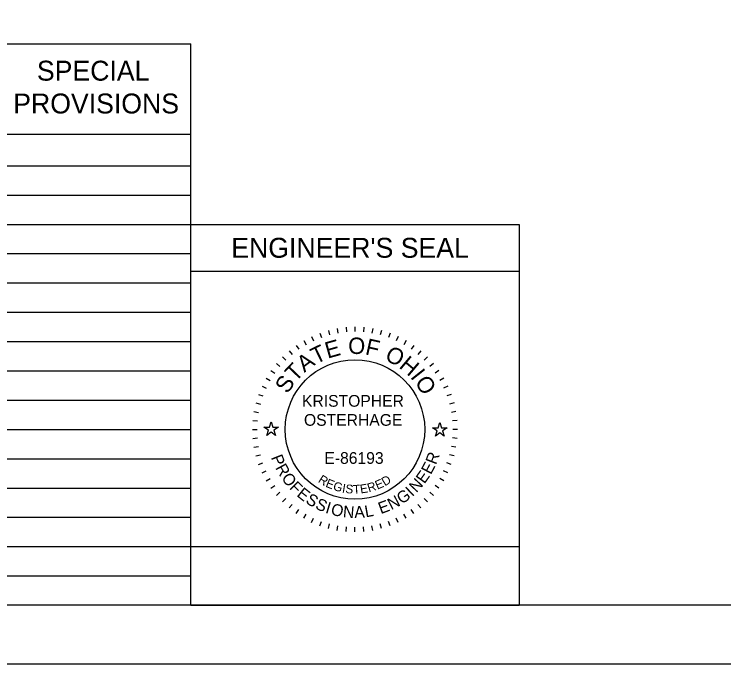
# Model space of a CAD drawing. Extents: x 0 to 64.8, y -5 to 22.
# Drawn here: x 22.09 to 28.15, y 0 to 5.54 of the extents above; entities that cross this region are included whole.
import ezdxf

# ---------------------------------------------------------------- set-up
doc = ezdxf.new("R2010")
doc.units = 0
for name, color, linetype in [('SH_Border', 7, 'Continuous'), ('SH_Cut_Line', 7, 'Continuous'), ('SH_Data', 7, 'Continuous'), ('SH_Text', 7, 'Continuous')]:
    doc.layers.add(name, color=color, linetype=linetype)

msp = doc.modelspace()

# ---------------------------------------------------------------- linework, layer by layer
at = {"layer": 'SH_Border'}
msp.add_lwpolyline([(1.5, 21.5), (33.5, 21.5), (33.5, 0.5), (1.5, 0.5)], close=True, dxfattribs=at)
at = {"layer": 'SH_Cut_Line'}
msp.add_lwpolyline([(0, 0), (34, 0), (34, 22), (0, 22)], close=True, dxfattribs=at)
at = {"layer": 'SH_Data'}
for p, q in [((10.15, 5.2917), (23.6, 5.2917)), ((23.6, 0.5), (23.6, 5.2917)), ((10.15, 4.5209), (23.6, 4.5209)), ((10.15, 4.25), (23.6, 4.25)), ((10.15, 4), (23.6, 4)), ((10.15, 3.75), (23.6, 3.75)), ((23.6, 0.5), (23.6, 3.75)), ((23.6, 3.75), (26.4, 3.75)), ((26.4, 3.75), (26.4, 0.5)), ((10.15, 3.5), (23.6, 3.5)), ((23.6, 3.35), (26.4, 3.35)), ((10.15, 3.25), (23.6, 3.25)), ((10.15, 3), (23.6, 3)), ((24.8481, 2.8617), (24.855, 2.8223)), ((24.9237, 2.8717), (24.9272, 2.8318)), ((25, 2.875), (25, 2.835)), ((25.0763, 2.8717), (25.0728, 2.8318)), ((25.1519, 2.8617), (25.145, 2.8223)), ((24.6302, 2.793), (24.6471, 2.7568)), ((24.7007, 2.8222), (24.7144, 2.7846)), ((24.7735, 2.8452), (24.7839, 2.8065)), ((25.2265, 2.8452), (25.2161, 2.8065)), ((25.2993, 2.8222), (25.2856, 2.7846)), ((25.3698, 2.793), (25.3529, 2.7568)), ((10.15, 2.75), (23.6, 2.75)), ((24.5625, 2.7578), (24.5825, 2.7231)), ((25.4375, 2.7578), (25.4175, 2.7231)), ((24.4376, 2.6703), (24.4633, 2.6396)), ((24.4981, 2.7168), (24.5211, 2.684)), ((25.5019, 2.7168), (25.4789, 2.684)), ((25.5624, 2.6703), (25.5367, 2.6396)), ((24.3813, 2.6187), (24.4096, 2.5904)), ((25.6187, 2.6187), (25.5904, 2.5904)), ((24.3297, 2.5624), (24.3604, 2.5367)), ((25.6703, 2.5624), (25.6396, 2.5367)), ((10.15, 2.5), (23.6, 2.5)), ((24.2832, 2.5019), (24.316, 2.4789)), ((25.7168, 2.5019), (25.684, 2.4789)), ((24.2422, 2.4375), (24.2769, 2.4175)), ((25.7578, 2.4375), (25.7231, 2.4175)), ((24.207, 2.3698), (24.2432, 2.3529)), ((25.793, 2.3698), (25.7568, 2.3529)), ((10.15, 2.25), (23.6, 2.25)), ((24.1778, 2.2993), (24.2154, 2.2856)), ((25.8222, 2.2993), (25.7846, 2.2856)), ((24.1548, 2.2265), (24.1935, 2.2161)), ((25.8452, 2.2265), (25.8065, 2.2161)), ((24.1383, 2.1519), (24.1777, 2.145)), ((25.8617, 2.1519), (25.8223, 2.145)), ((24.1283, 2.0763), (24.1682, 2.0728)), ((25.8717, 2.0763), (25.8318, 2.0728)), ((10.15, 2), (23.6, 2)), ((24.125, 2), (24.165, 2)), ((25.875, 2), (25.835, 2)), ((24.1283, 1.9237), (24.1682, 1.9272)), ((25.8717, 1.9237), (25.8318, 1.9272)), ((24.1383, 1.8481), (24.1777, 1.855)), ((25.8617, 1.8481), (25.8223, 1.855)), ((24.1548, 1.7735), (24.1935, 1.7839)), ((25.8452, 1.7735), (25.8065, 1.7839)), ((10.15, 1.75), (23.6, 1.75)), ((24.1778, 1.7007), (24.2154, 1.7144)), ((25.8222, 1.7007), (25.7846, 1.7144)), ((24.207, 1.6302), (24.2432, 1.6471)), ((25.793, 1.6302), (25.7568, 1.6471)), ((24.2422, 1.5625), (24.2769, 1.5825)), ((25.7578, 1.5625), (25.7231, 1.5825)), ((24.2832, 1.4981), (24.316, 1.5211)), ((25.7168, 1.4981), (25.684, 1.5211)), ((10.15, 1.5), (23.6, 1.5)), ((24.3297, 1.4376), (24.3604, 1.4633)), ((25.6703, 1.4376), (25.6396, 1.4633)), ((24.3813, 1.3813), (24.4096, 1.4096)), ((25.6187, 1.3813), (25.5904, 1.4096)), ((24.4376, 1.3297), (24.4633, 1.3604)), ((25.5624, 1.3297), (25.5367, 1.3604)), ((24.4981, 1.2832), (24.5211, 1.316)), ((24.5625, 1.2422), (24.5825, 1.2769)), ((25.4375, 1.2422), (25.4175, 1.2769)), ((25.5019, 1.2832), (25.4789, 1.316)), ((10.15, 1.25), (23.6, 1.25)), ((24.6302, 1.207), (24.6471, 1.2432)), ((24.7007, 1.1778), (24.7144, 1.2154)), ((25.2993, 1.1778), (25.2856, 1.2154)), ((25.3698, 1.207), (25.3529, 1.2432)), ((24.7735, 1.1548), (24.7839, 1.1935)), ((24.8481, 1.1383), (24.855, 1.1777)), ((24.9237, 1.1283), (24.9272, 1.1682)), ((25, 1.125), (25, 1.165)), ((25.0763, 1.1283), (25.0728, 1.1682)), ((25.1519, 1.1383), (25.145, 1.1777)), ((25.2265, 1.1548), (25.2161, 1.1935)), ((10.15, 1), (23.6, 1)), ((10.15, 0.75), (23.6, 0.75)), ((23.6, 0.5), (26.4, 0.5))]:
    msp.add_line(p, q, dxfattribs=at)
for points in [[(24.2236, 2.02), (24.2705, 2.02), (24.285, 2.0645), (24.2995, 2.02), (24.3464, 2.02), (24.3085, 1.9924), (24.323, 1.9478), (24.285, 1.9754), (24.247, 1.9478), (24.2615, 1.9924)], [(25.6627, 2.0146), (25.7096, 2.0146), (25.7241, 2.0591), (25.7386, 2.0146), (25.7855, 2.0146), (25.7476, 1.987), (25.7621, 1.9424), (25.7241, 1.97), (25.6861, 1.9424), (25.7006, 1.987)], [(23.6, 0.5), (23.6, 1), (26.4, 1), (26.4, 0.5)]]:
    msp.add_lwpolyline(points, close=True, dxfattribs=at)
msp.add_circle((25, 2), 0.595, dxfattribs=at)

# ---------------------------------------------------------------- texts
for s, height, p in [("ENGINEER'S SEAL", 0.17, (23.9448, 3.465)), ('KRISTOPHER', 0.1, (24.548, 2.1938)), ('OSTERHAGE', 0.1, (24.565, 2.0312)), ('E-86193', 0.1, (24.7391, 1.7063))]:
    msp.add_text(s, height=height, dxfattribs=at).set_placement(p)
for s, height, rotation, p in [('O', 0.14, 359.78119, (24.942, 2.6442)), ('T', 0.14, 25.71674, (24.6661, 2.554)), ('E', 0.14, 15.75706, (24.7669, 2.6034)), ('F', 0.14, 347.43619, (25.0811, 2.6417)), ('O', 0.14, 332.25863, (25.2463, 2.5981)), ('A', 0.14, 36.47472, (24.5685, 2.4819)), ('H', 0.14, 319.91363, (25.3684, 2.5316)), ('T', 0.14, 46.4344, (24.4917, 2.4)), ('I', 0.14, 308.36695, (25.4674, 2.4471)), ('S', 0.14, 57.19238, (24.426, 2.2981)), ('O', 0.14, 303.14906, (25.5061, 2.4028)), ('P', 0.1, 291.49398, (24.2823, 1.7619)), ('R', 0.1, 69.23216, (25.6913, 1.6936)), ('R', 0.1, 298.73106, (24.3181, 1.6733)), ('E', 0.1, 61.99508, (25.6472, 1.609)), ('E', 0.1, 54.75801, (25.5928, 1.5306)), ('O', 0.1, 306.46664, (24.3682, 1.5845)), ('R', 0.075, 327.82385, (24.6801, 1.554)), ('E', 0.075, 337.77772, (24.7439, 1.5128)), ('E', 0.075, 23.30524, (25.1909, 1.4856)), ('D', 0.075, 31.46601, (25.255, 1.5136)), ('N', 0.1, 47.02243, (25.5242, 1.455)), ('F', 0.1, 314.7068, (24.4343, 1.4983)), ('G', 0.075, 344.27273, (24.8082, 1.4848)), ('I', 0.075, 350.64643, (24.8868, 1.4634)), ('S', 0.075, 353.78581, (24.9155, 1.4581)), ('T', 0.075, 3.00609, (24.9852, 1.4505)), ('E', 0.075, 8.98261, (25.0492, 1.453)), ('R', 0.075, 17.68363, (25.1187, 1.4627)), ('E', 0.1, 321.43929, (24.497, 1.4354)), ('G', 0.1, 35.04687, (25.3997, 1.3581)), ('I', 0.1, 43.28703, (25.4876, 1.4221)), ('S', 0.1, 328.67637, (24.5722, 1.3766)), ('S', 0.1, 335.91345, (24.6541, 1.3276)), ('E', 0.1, 20.07421, (25.2203, 1.2767)), ('N', 0.1, 27.31129, (25.3097, 1.3102)), ('I', 0.1, 343.15053, (24.7416, 1.2894)), ('O', 0.1, 346.88592, (24.7884, 1.2741)), ('N', 0.1, 355.12608, (24.8946, 1.2512)), ('A', 0.1, 2.86166, (24.9964, 1.2439)), ('L', 0.1, 10.09874, (25.0917, 1.2494))]:
    msp.add_text(s, height=height, rotation=rotation, dxfattribs=at).set_placement(p)
at = {"layer": 'SH_Text'}
for s, p in [('SPECIAL', (22.2864, 4.9763)), ('PROVISIONS', (22.0843, 4.6963))]:
    msp.add_text(s, height=0.17, dxfattribs=at).set_placement(p)

doc.saveas('drawing.dxf')
